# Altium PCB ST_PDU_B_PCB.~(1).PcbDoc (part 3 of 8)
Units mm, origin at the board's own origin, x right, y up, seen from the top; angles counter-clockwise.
Board outline 200 x 200 mm, 6 copper layers (Top Layer, Layer 1, Layer 2, Layer 3, Layer 4, Bottom Layer), stack 3.194 mm thick; 894 components, 723 nets, 3233 pads, 4067 vias.
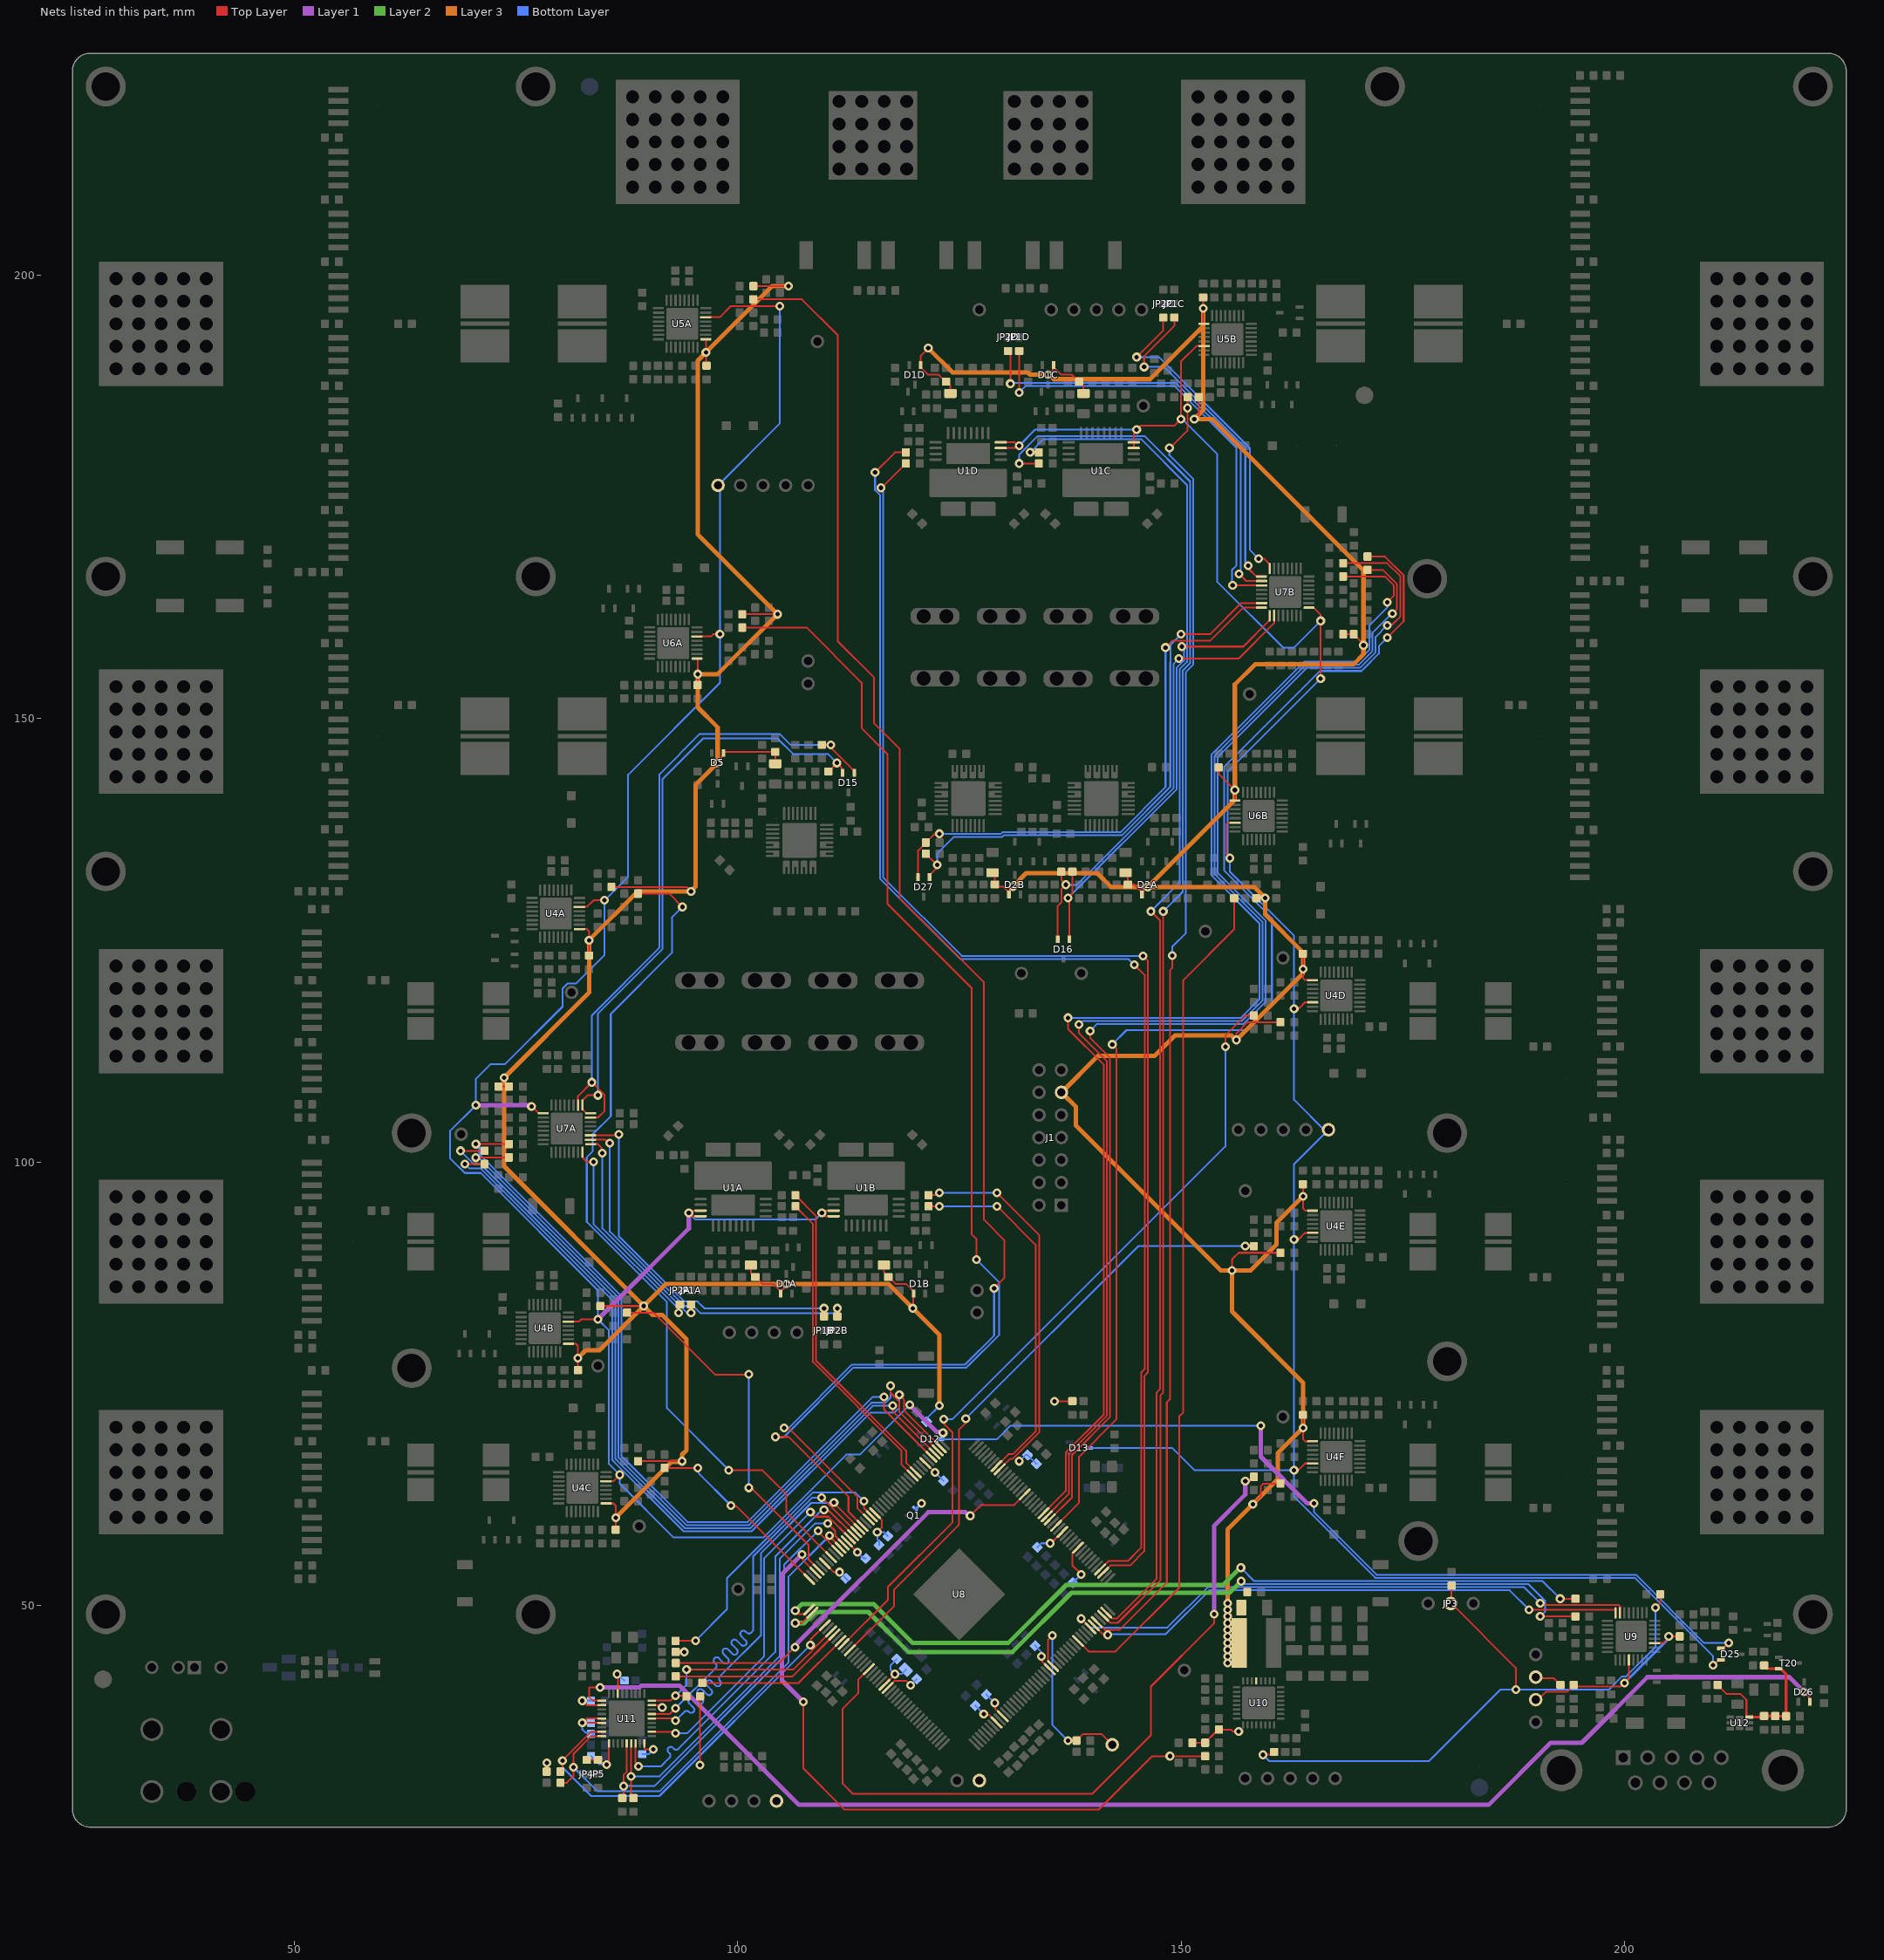
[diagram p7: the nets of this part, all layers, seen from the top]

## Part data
C1A C1B C1C C1D C5A C5B C5C C5D C8A C8B C15 C31A C31B C31C C31D C31E C31F C41A C41B C51A C51B C58A C58B C63 C64 C65 C66 C67 C68 C69 C70 C71 C72 C74 C109 C110 C111 C112 C114 C119: library part 100nF/50V_10%_0603, "100nF Ceramic capacitor", Package=0603, Tolerance=10%, Voltage=50V
C2A C2B C2C C2D C9A C9B C16: library part 1nF/50V_10%_0603, "1nF Ceramic capacitor", Package=0805, Tolerance=10%, Voltage=50V
C3A C3B C3C C3D C4A C4B C4C C4D C10A C10B C11A C11B C17 C18 C25A C25B C25C C25D C25E C25F C35A C35B C45A C45B C54A C54B C56A C56B C87 C99 C115 C116: library part 220nF/50V_10%_0603, "220nF Ceramic capacitor", Package=0603, Tolerance=10%, Voltage=50V
C6A C6B C6C C6D C7A C7B C7C C7D C13A C13B C14A C14B C20 C21 C22 C23 C32A C32B C32C C32D C32E C32F C42A C42B C52A C52B C73 C77 C79 C81 C83: library part 10nF/50V_10%_0603, "10nF Ceramic capacitor", Package=0603, Tolerance=10%, Voltage=50V
C12A C12B C19 C75 C84 C85 C92 C100: library part 2.2uF/16V_10%_0603, "2.2uF Ceramic capacitor", Package=0603, Tolerance=10%, Voltage=16V
C24A C24B C24C C24D C24E C24F C27A C27B C27C C27D C27E C27F C29A C29B C29C C29D C29E C29F C30A C30B C30C C30D C30E C30F C34A C34B C37A C37B C39A C39B C40A C40B C44A C44B C47A C47B C49A C49B C50A C50B C57A C57B C113 C118: library part 470nF/50V_10%_0603, "470nF Ceramic capacitor", Package=0603, Tolerance=10%, Voltage=50V
C26A C26B C26C C26D C26E C26F C28A C28B C28C C28D C28E C28F C36A C36B C38A C38B C46A C46B C48A C48B C88 C89 C90 C91 C108 C122 C123 C124: library part 1uF/50V_10%_0603, "1uF Ceramic capacitor", Package=0603, Tolerance=10%, Voltage=50V
C33A C33B C33C C33D C33E C33F C43A C43B C53A C53B C59A C59B C106: library part 1uF/16V_10%_0603, "1uF Ceramic capacitor", Package=0603, Tolerance=10%, Voltage=16V
C55A C55B: library part 22uF/50V_20%_CES_D_6.3, "22uF Electrolytic capacitor (EEHZC1H220P)", Tolerance=20%, Voltage=50V
C60 C61 C120 C121: library part 10pF/50V_10%_0603, "10pF Ceramic capacitor", Package=0603, Tolerance=10%, Voltage=50V
C62: library part 4,7uF/16V_10%_0805, "4,7uF Ceramic capacitor", Supplier Part Number 1=2112841, Tolerance=10%, Voltage=16V
C76 C78 C80 C82: library part 47nF/50V_10%_0603, "47nF Ceramic capacitor", Package=0603, Tolerance=10%, Voltage=50V
C86 C93 C94 C96 C97 C101 C102 C103 C104: library part 10uF/50V_10%_1206, "10uF Ceramic capacitor", Tolerance=10%, Voltage=50V
C95 C98: library part 100uF/50V_20%_CES_D_10, "100uF Electrolytic capacitor (EEHZC1H101V)", Tolerance=20%, Voltage=50V
C105 C107: library part 2,2uF/50V_10%_0805, "2,2uF Ceramic capacitor", Package=0805, Tolerance=10%, Voltage=50V
C117: library part 4,7nF/50V_10%_0603, "4.7nF Ceramic capacitor", Package=0603, Tolerance=10%, Voltage=50V
C125A C125B C125C C125D C125E C125F C126A C126B C127A C127B: library part 22uF/50V_20%_CES_D_6.3, "22uF Electrolytic capacitor (EEHZC1H220V)", Tolerance=20%, Voltage=50V
CR1: "No Description Available", Mfr_Name=STMicroelectronics
CR2: "ESD protection for automotive ethernet"
D1A D1B D1C D1D D2A D2B D5 D6A D6B D6C D6D D6E D6F D7A D7B D11A D11B D12 D13 D20 D21 D22 D23 D24 D28A D28B: "Automotive small signal Schottky diodes", Current=0.3A
D3A D3B D4 D25: "Automotive small signal dual Schottky diodes with common anode", Current=0.3A
D8A D8B D8C D8D D8E D8F D9A D9B D10A D10B: "40V/1A Automotive Schottky Diode STPS1L40-Y", Current=1A
D14A D14B D17 D18 D19: "60V/3A Automotive Schottky Diode STPS360-Y", Current=3A
D15 D16 D26 D27: library part BAT54C, "Automotive small signal dual Schottky diodes with common cathode", Current=0.3A
J2: "Header, 9-Pin, Right Angle", Supplier Part Number 1=1653975
J3: library part CMP-0078655-1, "Conn 1-Port 90° MATEnet Header, Code B", 2B Part Number=2BCONNECTPF00506, Manuf Code=2304372-2, Manufacturer="TE Connectivity"
JP1A JP1B JP1C JP1D JP2A JP2B JP2C JP2D: library part JUMP_3_PIN
JP6: Supplier Part Number 1="Header 2.54mmm 2way"
L1: library part 74438367100, "WE-MAPI, size 5030, 10uH, 3.3A, 70.2mOhm", Case/Size Code=5030, DC resistance=61mOhm, DC Resistance Max=70.2mOhm, Manufacturer="Wurth Elektronik", Operating Temperature Max=125°C, Operating Temperature Min=-40°C, Rated Current=3.3A, Saturation Current=4.8A, Self Resonant Frequency=13MHz
L2: library part LPS6235-153, "SMD Inductor; 15uH/20%/2,0A sat.; 6x6x3,5mm", DC resistance="0,125 Ohm", Rated Current=1.22A, Saturation Current=2,0A, Tolerance=20%
L3: library part 100uH/0,15A_+50%/-30%_1812, "Common Mode Choke for CAN", DC resistance="1,5 Ohm", Rated Current=0,15A, Supplier Part Number 1=1644874, Tolerance=+50/-30
L4: "Automotive ethernet CMMC", Mfr_Name=Murata
LED1: library part LED/RED_00603, Current=30mA
LED2 LED8 LED9: library part LED/ORANGE_0603, Current=30mA
LED3 LED4 LED5 LED6 LED7: library part LED/GREEN_0603, Current=30mA
LED10: library part LED/ORANGE_0603, "Orange LED", Current=30mA
P1 P2 P7 P8 P14 P15: "Pressfit M8 screw power connector (max 170A) with protector"
P3 P4 P5 P9 P10 P11: "Pressfit M6 screw power connector (max 80A) with protector"
P6 P12: "MTCon G&H 8pin power connector (max 40A/pin). Pressfit", Supplier Part Number 1=2035533
P13 P16: "Pressfit M5 screw power connector (max 80A) with protector"
Q1: "NPN Medium Power Transistor", Package=DFN2020-3
Q2: "N-Channel Enhancement Mode Vertical DMOS FET", Package=SOT23, Supplier Part Number 1=9845330
R1A R1B R1C R1D R15A R15B R29: library part 330R/150V_1%_0805, "Resistor SMD", Package=0805, Power Rating Per Resistor=125mW, Tolerance=1%, Voltage=150V
R2A R2B R2C R2D R16A R16B R30 R152 R153: library part 100R/0.1W_5%_0603, "Resistor SMD", Package=0603, Power=0.1W, Tolerance=5%
R3A R3B R3C R3D R17A R17B R31 R101A R101B: library part 330R/0.1W_5%_0603, "Resistor SMD", Package=0603, Power=0.1W, Tolerance=5%
R4A R4B R4C R4D R18A R18B R32: library part 120R/0.1W_5%_0603, "Resistor SMD", Package=0603, Power=0.1W, Tolerance=5%
R5A R5B R5C R5D R19A R19B R28A R28B R33 R42 R127 R154 R157 R163 R164 R192: library part 4k7/0.1W_5%_0603, "Resistor SMD", Package=0603, Power=0.1W, Tolerance=5%
R6A R6B R6C R6D R7A R7B R7C R7D R10A R10B R10C R10D R11A R11B R11C R11D R20A R20B R21A R21B R22A R22B R23A R23B R24A R24B R34 R35 R36 R37 R38 R48A R48B R48C R48D R48E R48F R57A R57B R57C R57D R57E R57F R58A R58B R58C R58D R58E R58F R59A R59B R59C R59D R59E R59F R67A R67B R77A R77B R78A R78B R80A R80B R87A R87B R97A R97B R98A R98B R99A R99B R102A R102B R103A R103B R104A R104B R105A R105B R106A R106B R107A R107B R156 R159 R162 R193 R194 R195 R196: library part 2k7/0.1W_5%_0603, "Resistor SMD", Package=0603, Power=0.1W, Tolerance=5%
R8A R8B R8C R8D R9A R9B R9C R9D R46 R52 R65 R123 R129 R130 R146 R147 R148 R149 R150 R151 R160 R161 R169 R185 R186 R188: library part 15k/0.1W_5%_0603, "Resistor SMD", Package=0603, Power=0.1W, Tolerance=5%
R12A R12B R12C R12D R13A R13B R13C R13D R25A R25B R26A R26B R39 R40 R49A R49B R49C R49D R49E R49F R51A R51B R51C R51D R51E R51F R68A R68B R70A R70B R88A R88B R90A R90B R108A R108B R109A R109B: library part 5k6/0.1W_5%_0603, "Resistor SMD", Package=0603, Power=0.1W, Tolerance=5%
R14A R14B R14C R14D R27A R27B R41 R50A R50B R50C R50D R50E R50F R69A R69B R89A R89B R110A R110B R155 R165: library part 180R/0.1W_5%_0603, "Resistor SMD", Package=0603, Power=0.1W, Tolerance=5%
R43A R43B R43C R43D R43E R43F: library part CurrentShunt_9W_3921, "High current shunt size 3921", Power Rating Per Resistor=9W, Voltage=150V
R44A R44B R44C R44D R44E R44F R47A R47B R47C R47D R47E R47F R53A R53B R53C R53D R53E R53F R61A R61B R62A R62B R63A R63B R66A R66B R72A R72B R74A R74B R79A R79B R81A R81B R83A R83B R86A R86B R92A R92B R95A R95B R100A R100B: library part 1R/0.1W_5%_0603, "Resistor SMD", Package=0603, Power=0.1W, Tolerance=5%
R45A R45B R45C R45D R45E R45F R55A R55B R55C R55D R55E R55F R64A R64B R75A R75B R84A R84B R94A R94B R122 R128 R166 R170 R171 R173 R174 R175 R176 R179 R180 R182: library part 47k/0.1W_5%_0603, "Resistor SMD", Package=0603, Power=0.1W, Tolerance=5%
R54A R54B R54C R54D R54E R54F R73A R73B R93A R93B: Package=0805, Supplier Part Number 1=1299914
R56A R56B R56C R56D R56E R56F R76A R76B R96A R96B R134 R172 R181 R190 R191: library part 10k/0.1W_5%_0603, "SMD Resistor Automotive", 2B Part Number=2BRESCHIPSF00800, Manufacturer=PANASONIC, Manufacturer P/N=ERJP03F1002V, Package=0603, Power=0.1W, Tolerance=1%
R60A R60B R82A R82B: library part CurrentShunt_15W_5930, "ISA-WELD precission resistor  BVE size 5630", Package=5930, Power Rating Per Resistor=15W, Voltage=150V
R71: library part 0R/0.1W_5%_0603, "Resistor SMD 0805", Package=0603, Power=0.1W, Tolerance=5%
R85 R91: library part 10k/0.1W_5%_0603, "Resistor SMD 0603", 2B Part Number=2BRESCHIPSF00800, Manufacturer=PANASONIC, Manufacturer P/N=ERJP03F1002V, Package=0603, Power=0.1W, Tolerance=1%
R111 R112 R113 R114 R115 R116 R117 R118 R197A R197B R198A R198B: library part 0R/0.1W_5%_0603, "Resistor SMD", Package=0603, Power=0.1W, Tolerance=5%
R119 R120 R121 R124 R125 R126 R131 R132 R133 R135 R136 R137 R139 R140 R141 R184: library part 47R/0.1W_5%_0603, "Resistor SMD", Package=0603, Power=0.1W, Tolerance=5%
R138 R142 R202: library part 1k5/0.1W_5%_0603, "Resistor SMD", Package=0603, Power=0.1W, Tolerance=5%
R143 R144 R145 R183: library part 100k/0.1W_5%_0603, "SMD Resistor", 2B Part Number=2BRESCHIPSF00800, Manufacturer=PANASONIC, Manufacturer P/N=ERJP03F1002V, Package=0603, Power=0.1W, Tolerance=1%
R158 R167 R168: library part 3k3/0.1W_5%_0603, "Resistor SMD", Package=0603, Power=0.1W, Tolerance=5%
R177 R178 R187: library part 1k/0.1W_5%_0603, "Resistor SMD", Package=0603, Power=0.1W, Tolerance=5%
R189: library part 30k/0.1W_5%_0603, "Resistor SMD", Package=0603, Power=0.1W, Tolerance=5%
R199: library part 360k/0.1W_5%_0603, "SMD Resistor", 2B Part Number=2BRESCHIPSF00800, Manufacturer=PANASONIC, Manufacturer P/N=ERJP03F1002V, Package=0603, Power=0.1W, Tolerance=1%
R200 R201: library part 200k/0.1W_5%_0603, "SMD Resistor", 2B Part Number=2BRESCHIPSF00800, Manufacturer=PANASONIC, Manufacturer P/N=ERJP03F1002V, Package=0603, Power=0.1W, Tolerance=1%
R203: library part 47k/0.1W_5%_0603, "Resistor SMD 0603", Package=0603, Power=0.1W, Tolerance=5%
R204 R205 R206A R206B: library part 47R/0.1W_5%_0603, "Resistor SMD 0603", Package=0603, Power=0.1W, Tolerance=5%
T1A T1B T1C T1D T2A T2B T3: "NPN", Supplier Part Number 1=1260803
T4A T4B T4C T4D T4E T4F T5A T5B T5C T5D T5E T5F T6A T6B T6C T6D T6E T6F T7A T7B T8A T8B T9A T9B T10A T10B T11A T11B T12A T12B T13A T13B T14A T14B T15A T15B T16A T16B T17A T17B T18A T18B T19A T19B: library part STL059N4S8AG, "Automotive N‑channel logic level 40 V, 0.59 mΩ max., 420 A Smart STripFET F8 / Power MOSFET in a PowerFLAT 5x6 package"
T20: "PNP", Supplier Part Number 1=1902487
TP1 TP2 TP3 TP4 TP5 TP6 TP7 TP8 TP9 TP10 TP11 TP12 TP13 TP14 TP15 TP16 TP17 TP18 TP19 TP20 TP21 TP22 TP23 TP24 TP25 TP26 TP27 TP28 TP29 TP30 TP31 TP32 TP33 TP34 TP35 TP36 TP37 TP38 TP39 TP40 TP41 TP42 TP43 TP44 TP45 TP46 TP47 TP48 TP49 TP50 TP51 TP52 TP53: library part "Test Point_1", "PCB ring test point - black (drill 1.32mm)", 2B Part Number=2BCONTESTPF00021, Manuf Code=262-2214, Manufacturer="RS PRO"
Tr_d3 Tr_d4 Tr_d10 Tr_d13: "30V 3000W unidirectional TVS in SMC", Power Rating=3000W
Tr_d18 Tr_d19: "39V 1500W unidirectional TVS in SMC", Power Rating=1500W
Tr_d20 Tr_d21: "18V 1500W unidirectional TVS in SMC", Power Rating=1500W, Supplier Part Number 1=9885676
U7A U7B: "Octa channel Smart P-channel MOSFET device. Used for standby power with STi2Fuse devices"
U8: "Chorus 6M, 3 cores, 6MB flash, LQFP176 package"
U9: library part SPSB081
U10: "SPSA068 PMIC with buck and precise voltage reference for MCU applications"
U11: "100BASE-T1 PHY for Automotive Ethernet"
U12: "Adjustable 200mA LDO"
X1: library part CX3225CA40000D0HSSZ1, "CRYSTAL 40.000MHZ 8PF SMD Automotive -40/+125"
X2: library part CX3225CA25000D0HSSZ1, "CRYSTAL 25.000MHZ 8PF SMD Automotive -40/+125"
ZD1A ZD1B ZD1C ZD1D ZD1E ZD1F ZD2A ZD2B ZD3A ZD3B: "5,6V Zener Diode", Power Rating=200mW

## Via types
v1: diameter 0.65/1/1/1/1/0.65 (per signal layer), hole 0.5, Top Layer to Bottom Layer, 3739 vias
v2: diameter 0.65/1/1/1/1/0.65 (per signal layer), hole 0.5, Top Layer to Bottom Layer, tented both sides, 296 vias
v3: diameter 0.65, hole 0.5, Top Layer to Bottom Layer, 32 vias

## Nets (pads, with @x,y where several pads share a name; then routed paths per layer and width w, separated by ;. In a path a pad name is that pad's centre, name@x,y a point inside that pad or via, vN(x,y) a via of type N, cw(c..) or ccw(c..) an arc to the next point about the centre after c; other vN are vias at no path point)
3V3: C1A.2 C1B.2 C1C.2 C1D.2 C8A.2 C8B.2 C15.2 C31A.2 C31B.2 C31C.2 C31D.2 C31E.2 C31F.2 C41A.2 C41B.2 C51A.2 C51B.2 C58A.2 C58B.2 C62.2 C63.2 C64.2 C65.2 C66.2 C67.2 C68.2 C69.2 C70.2 C71.2 C72.2 C73.2 C74.2 C86.2 C87.2 C109.2 C110.2 C114.2 C115.2 C116.2 C118.2 D1A.1 D1B.1 D1C.1 D1D.1 D2A.1 D2B.1 D5.1 J1.11 JP4.3 JP5.2 JP6.2 L1.2 LED10.A Q1.2 R1A.2 R1B.2 R1C.2 R1D.2 R15A.2 R15B.2 R29.2 R55A.1 R55B.1 R55C.1 R55D.1 R55E.1 R55F.1 R75A.1 R75B.1 R94A.1 R94B.1 R101A.1 R101B.1 R122.1 R127.1 R128.1 R158.1 R167.1 R168.1 R176.1 R181.2 R182.1 R193.2 TP3.1 TP6.1 U4A.1 U4B.1 U4C.1 U4D.1 U4E.1 U4F.1 U5A.1 U5B.1 U6A.1 U6B.1 U8.25 U8.26 U8.52 U8.54 U8.69 U8.99 U8.104 U8.139 U8.155 U8.164 U8.171 U10.5 U11.7 U11.11 U11.14 U11.15 U11.19 U11.27 U11.35 | length 752.4
  Top Layer w0.2: v1(73.675,109.5) 73.608,109.433 73.608,109.108 73.025,108.525 R101A.1@73.025,108.5 C58A.2@74.225,108.5 ; R176.1@78.475,31.25 78.5,31.275 v1(78.5,32.25) ; U4B.1@80.927,79.5 81.75,79.5 82,79.25 v1(82,77.887) C31B.2@82,76.525 ; U4A.1@82.177,126.25 83,126.25 83.25,126 v1(83.25,125) C31A.2@83.25,123.275 C31A.2@83.25,123.144 ; v1(82.5,39.25) 83,38.75 U11.11@84.3,38.75 ; JP4.3@83,32.575 JP5.2@84.25,32.575 84.575,32.25 84.878,32.25 85.097,32.032 v1(85.218,32.032) 85.218,32.153 85.5,32.435 U11.19@85.5,34.05 ; R55B.1@84.552,83.75 v1(89.425,83.75) ; U11.15@84.683,36.75 v1(82.5,36.75) 83,37.25 U11.14@84.683,37.25 ; U4C.1@85.177,61.5 86,61.5 86.25,61.25 v1(86.25,59.888) C31C.2@86.25,58.525 C31C.2@86.25,58.394 ; R55A.1@85.775,131 94.25,131 v1(94.75,130.5) ; v1(86.425,42.25) 86.5,42.175 U11.7@86.5,40.45 ; R55C.1@88.775,66.25 v1(93.75,66.25) ; U11.27@89.5,34.05 89.5,33.867 89.617,33.75 v1(90.5,33.75) ; U11.35@90.317,38.75 91.128,38.75 91.378,38.5 v1(91.5,38.5) ; R182.1@93.025,44.75 v1(94,44.75) ; U6A.1@95.427,156.75 95.473,156.75 95.5,156.723 v1(95.5,155) C51A.2@95.5,153.775 ; v1(95.75,32) 95.775,32.025 R181.2@95.775,39.75 ; C41A.2@96.427,189.775 v1(96.427,191.263) U5A.1@96.427,192.75 ; v1(97.75,145) 97.836,145.086 97.836,145.312 98.4,145.876 D5.1@98.4,146.108 98.4,146.147 98.503,146.25 104.225,146.25 C15.2@104.25,146.225 R29.2@104.25,144.893 ; R94A.1@100.525,161.75 v1(104.5,161.75) ; R1A.2@101.5,88.357 101.5,87.507 101.982,87.025 C1A.2@102,87.025 ; R75A.1@101.775,198.75 v1(105.75,198.75) ; C1A.2@102.025,87.025 102.8,86.25 104,86.25 104.747,85.503 D1A.1@104.747,85.271 ; D1A.1@104.747,85.245 D1A.1@104.747,85.271 ; v1(105.5,86.25) 105.414,86.164 105.414,85.938 D1A.1@104.747,85.271 ; U8.171@109.843,54.74 110.833,53.75 v1@111.25,53.75 ; U8.164@112.318,57.214 112.318,57.198 113.5,56.016 v1(113.5,56) ; U8.155@115.5,60.396 116.25,59.646 116.25,58.75 v1(115.75,58.25) ; R1B.2@116.5,88.357 116.5,87.525 116.517,87.508 116.633,87.392 116.633,87.374 116.982,87.025 C1B.2@117,87.025 117.025,87.025 117.8,86.25 119,86.25 119.747,85.503 119.747,85.245 D1B.1@119.85,85.142 119.8,85.092 119.8,83.55 v1(119.75,83.5) ; U8.25@116.561,41.043 116.561,41.052 117.75,42.241 v1(117.75,42.25) ; U8.26@116.914,40.689 117.725,41.5 119,41.5 v1(119.5,41) ; U8.139@121.157,66.053 121.177,66.053 122.23,65 v1(122.25,65) ; v1(121.5,191.75) 120.65,190.9 D1D.1@120.65,189.858 120.753,189.755 120.753,189.497 121.5,188.75 122.7,188.75 123.475,187.975 C1D.2@123.5,187.975 123.518,187.975 124,187.493 R1D.2@124,186.643 ; v1(127.75,37.75) 127.836,37.664 128.333,37.664 U8.52@129.197,36.8 ; R15B.2@128.75,132.607 128.98,132.377 128.98,131.295 C8B.2@129,131.275 129.238,131.037 129.936,131.037 130.6,130.374 D2B.1@130.6,130.142 130.673,130.214 130.673,130.673 v1(131.064,131.064) ; v1(129,39) 129.036,38.964 129.036,38.375 U8.54@129.904,37.507 ; v1(134.25,44.25) 134.336,44.164 134.336,43.682 U8.69@135.207,42.811 ; v1(135,188.75) 135.547,189.297 135.547,189.755 D1C.1@135.65,189.858 135.753,189.755 135.753,189.497 136.5,188.75 137.7,188.75 138.475,187.975 C1C.2@138.5,187.975 138.518,187.975 139,187.493 R1C.2@139,186.643 ; v1(135.25,57) 135.346,57 U8.104@136.621,58.275 ; v1(135.75,73) 137.725,73 LED10.A@137.75,73.025 ; U8.99@138.389,56.507 138.389,56.48 137.75,55.841 137.75,54.5 v1(138.75,53.5) ; R15A.2@143.5,132.5 143.697,132.5 144,132.197 C8A.2@144,131.275 144.699,131.275 D2A.1@145.6,130.374 ; D2A.1@145.6,130.142 D2A.1@145.6,130.374 ; v1(146.25,131) 146.226,131 D2A.1@145.6,130.374 ; R168.1@151.275,34.5 R167.1@152.725,34.5 152.725,34.525 153.833,35.633 153.926,35.633 154.275,35.982 R158.1@154.275,36 155.653,36 155.878,35.775 v1(156.505,35.775) ; v1(151.5,183.75) 152,184.25 R75B.1@152,186.225 ; C41B.2@152.5,197.475 v1(152.5,196.25) 152.5,194.527 152.527,194.5 U5B.1@152.573,194.5 ; C51B.2@154.25,144.475 154.25,143.75 v1(156.073,141.927) U6B.1@156.073,140.75 ; v1(155.75,87.75) 155.75,89 156.5,89.75 R55E.1@161.225,89.75 ; v1(156.25,113.75) 156.25,114.5 157.5,115.75 R55D.1@161.225,115.75 ; v1(158.093,61.407) 159,62.313 159,63.438 159.287,63.725 161.2,63.725 R55F.1@161.225,63.75 ; R94B.1@158.5,129.725 158.525,129.75 v1(159.5,129.75) ; C31F.2@163.75,71.606 C31F.2@163.75,71.475 v1(163.75,70) 163.75,68.75 164,68.5 U4F.1@164.823,68.5 ; C31E.2@163.75,97.475 v1(163.75,96.113) 163.75,94.75 164,94.5 U4E.1@164.823,94.5 ; C31D.2@163.75,123.606 C31D.2@163.75,123.475 v1(163.75,121.75) 163.75,120.75 164,120.5 U4D.1@164.823,120.5 ; C58B.2@168.275,159.5 R101B.1@169.475,159.5 169.475,159.468 170.575,158.368 v1(170.575,158.25) ; TP6.1@190.123,41.787 191.999,41.787 192.761,41.025 R193.2@192.786,41.025
  Layer 3 w0.5: v1(82,77.887) 82.863,78.75 84.425,78.75 v1(89.425,83.75) ; v1(86.25,59.888) 92.517,66.154 93.654,66.154 v1(93.75,66.25) 93.75,67 94.25,67.5 94.25,80 91.5,82.75 90.425,82.75 v1(89.425,83.75) ; v1(105.75,198.75) 105.741,198.741 103.906,198.741 v1(96.427,191.263) 95.5,190.335 95.5,170.75 v1(104.5,161.75) 97.75,155 v1(95.5,155) 95.5,151.25 97.75,149 v1(97.75,145) 95.25,142.5 95.25,131.043 94.75,130.543 v1(94.75,130.5) 88.75,130.5 v1(83.25,125) 83.25,119.075 v1(73.675,109.5) 73.675,99.5 v1(89.425,83.75) ; v1(121.5,191.75) 124.25,189 132.741,189 132.991,188.75 v1(135,188.75) 135.135,188.75 135.635,188.25 146.5,188.25 152.5,194.25 ; v1(122.75,72.5) 122.75,80.5 v1(119.75,83.5) 117,86.25 v1(105.5,86.25) 91.925,86.25 v1(89.425,83.75) ; v1(131.064,131.064) 132.55,132.55 140.554,132.55 142.104,131 v1(146.25,131) ; v1(152.5,196.25) 152.5,194.25 ; v1(155.25,50.25) 155.25,58.563 v1(158.093,61.407) 160.922,64.235 160.922,67.172 v1(163.75,70) 163.75,75.125 155.75,83.125 v1(155.75,87.75) ; v1(163.75,96.113) 160.75,93.113 160.75,90.662 157.838,87.75 v1(155.75,87.75) ; v1(146.25,131) 158.25,131 v1(159.5,129.75) 159.5,127.875 163.75,123.625 v1(163.75,121.75) 163.712,121.712 163.712,121.212 v1(156.25,113.75) 156.196,113.75 155.696,114.25 149.312,114.25 147.012,111.95 140.64,111.95 J1.11@136.52,107.83 138.16,106.19 138.16,104.077 154.487,87.75 v1(155.75,87.75) ; v1(146.25,131) 156.035,140.785 156.035,141.889 v1(156.073,141.927) 156.073,153.823 158.348,156.098 169.437,156.098 170.575,157.237 v1(170.575,158.25) 170.575,166.675 153.5,183.75 v1(151.5,183.75) 152.5,184.75 152.5,194.25
  Bottom Layer w0.2: v1(82.5,39.25) C116.2@83.475,39.25 C116.2@83.7,39.25 ; C110.2@83.475,33 83.475,32.982 83.824,32.633 83.842,32.633 84.368,32.107 85.143,32.107 v1(85.218,32.032) ; C114.2@83.725,35.5 83.567,35.658 82.842,35.658 82.5,36 v1(82.5,36.75) C115.2@83.725,36.75 ; v1(86.425,42.25) 86.493,42.25 87.218,41.525 C118.2@87.25,41.525 ; C109.2@89.25,33.225 89.975,33.225 v1(90.5,33.75) ; v1(111.5,53.75) C67.2@112.202,53.048 C67.2@112.452,52.798 ; v1(113.5,56) 114.202,55.298 C74.2@114.452,55.298 ; C73.2@115.952,56.798 115.952,57.221 115.75,57.423 v1(115.75,58.25) 116.5,58.25 C72.2@116.952,57.798 ; C63.2@117.952,43.952 117.25,43.25 117.25,42.75 v1(117.75,42.25) 118.487,42.25 C62.2@118.981,42.743 ; v1(119.5,41) C70.2@120.202,41.702 ; R122.1@121.298,70.702 121.298,71.048 v1(122.75,72.5) ; v1(122.25,65) C66.2@123.202,64.048 ; C69.2@126.798,38.702 v1(127.75,37.75) ; C68.2@128.048,39.952 v1(129,39) ; v1(131.75,66.25) 132.452,66.952 R127.1@132.702,66.952 R128.1@133.702,65.952 ; C64.2@133.548,45.452 134.25,44.75 v1(134.25,44.25) ; C71.2@133.798,56.548 134.25,57 v1(135.25,57) ; C65.2@137.798,52.548 v1(138.75,53.5)
  Bottom Layer w0.3: Q1.2@120.018,60.901 120.048,60.872 120.122,60.872 v1(120.75,61.5)
  other v1: 155.25,43.5 155.25,44.25 155.25,45 155.25,45.75 155.25,46.5 155.25,47.25 155.25,48 155.25,48.75 155.25,49.5
3V3_STB: C106.2 R171.1 R194.2 R199.1 R200.2 T20.2 U12.6 | length 18.1
  Top Layer w0.2: R194.2@210.5,41.025 210.525,41.025 211.55,40 213.098,40 213.75,39.348 213.75,37.725 213.765,37.71 213.765,37.5 213.865,37.4 U12.6@214.075,37.4 ; R200.2@215.625,37.525 R200.2@215.75,37.525
  Top Layer w0.3: U12.6@214.075,37.4 215.625,37.4 R200.2@215.75,37.525 C106.2@217,37.525 217.012,37.513 218.212,37.513 R199.1@218.225,37.5 218.225,42.249 217.624,42.85 T20.2@217.392,42.85 216.15,42.85 215.775,43.225 R171.1@215.75,43.225
5V: C92.2 R192.1 TP5.1 U9.3 U9.28 | length 25.2
  Top Layer w0.2: TP5.1@189.992,39.116 191.126,40.25 193.538,40.25 193.919,40.631 193.919,40.676 194.029,40.786 194.286,40.786 R192.1@194.286,41.025 ; R192.1@194.071,40.965 R192.1@194.148,40.888 ; R192.1@194.071,41.025 R192.1@194.286,41.025 ; R192.1@194.13,40.888 R192.1@194.148,40.888 ; U9.28@200.5,43.848 200.5,41.75 v1(200,41.25) 199.966,41.25 199.541,40.825 194.361,40.825 194.286,40.75 R192.1@194.148,40.888 ; U9.3@203.402,45.75 204.372,45.75 205,46.378 v1(205,46.5) C92.2@206.225,46.5 ; R192.1@194.148,40.888 R192.1@194.286,41.025
  Bottom Layer w0.3: v1(200,41.25) 204.933,46.183 204.933,46.433 v1(205,46.5)
CAN1_RX: R153.1 U8.2 | length 99.6
  Top Layer w0.2: v1(106.5,48) 107.254,48 U8.2@108.429,49.175 ; v1(190.5,48.75) R153.1@194.475,48.75
  Layer 2 w0.5: v1(106.5,48) 107.5,48 108.75,49.25 114.75,49.25 119.25,44.75 130.996,44.75 137.656,51.409 155.465,51.409 v1(156.778,52.722)
  Bottom Layer w0.2: v1(156.778,52.722) 157.1,52.4 189.163,52.4 191.075,50.488 191.075,49.325 v1(190.5,48.75)
CAN1_TX: R152.2 U8.1 | length 97
  Top Layer w0.2: v1(106.5,49.4) 106.9,49 107.499,49 108.027,49.528 U8.1@108.075,49.528 ; v1(192.75,50.75) R152.2@194.475,50.75
  Layer 2 w0.5: v1@106.5,49.404 107.246,50.15 115.35,50.15 119.75,45.75 130.5,45.75 137.059,52.309 154.738,52.309 156.679,54.25 v1@156.746,54.25
  Bottom Layer w0.2: v1(156.75,54.25) 158.25,52.75 190.75,52.75 v1(192.75,50.75)
DEBUG: JP3.1 R71.2 R85.2 R91.1 | length 72.3
  Top Layer w0.2: v1(159.25,33.15) 159.294,33.194 160.219,33.194 R91.1@160.5,33.475 ; R71.2@180.5,52.225 180.5,50.293 JP3.1@180.408,50.202 180.502,50.202 187.75,42.954 v1(187.75,40.5) ; v1(203.5,49.75) 204.025,50.275 R85.2@204.025,51.25
  Bottom Layer w0.2: v1(159.25,33.15) 159.975,32.425 177.925,32.425 186,40.5 v1(187.75,40.5) 198.25,40.5 199.75,42 200.184,42 203.5,45.316 v1(203.5,49.75)
DI0_A14: R103A.2 U8.137 | length 93.2
  Top Layer w0.2: v1(70.5,102) R103A.2@74.225,102 ; v1(116.5,73.5) 116.5,72.124 U8.137@121.864,66.76
  Bottom Layer w0.2: v1(70.5,102) 70.9,101.6 70.9,100.865 86.9,84.865 86.9,66.855 87.15,66.605 87.15,66.6 94.35,59.4 101.15,59.4 115.253,73.503 116.497,73.503 v1(116.5,73.5)
DI0_B14: R103B.2 U8.110 | length 149.9
  Top Layer w0.2: U8.110@134.5,60.396 137,62.896 137,67.235 141.3,71.535 141.3,110.95 137.25,115 v1(137.25,116.25) ; R103B.2@168.275,166 173,166 174,165 174,163.86 v1(173.24,163.1)
  Bottom Layer w0.2: v1(137.25,116.25) 156.745,116.25 158.85,118.355 158.85,126.895 153.45,132.295 153.45,145.95 163.9,156.4 169.9,156.4 171.25,157.75 171.25,160.5 173.24,162.49 v1(173.24,163.1)
DI1_A14: R104A.2 U8.136 | length 92.7
  Top Layer w0.2: v1(68.75,101.25) R104A.2@71.475,101.25 ; v1(117.5,72.5) 117.5,71.831 U8.136@122.218,67.114
  Bottom Layer w0.2: v1(68.75,101.25) 70.25,99.75 71.025,99.75 86.2,84.575 86.2,66.565 86.45,66.315 86.45,66.3 94.05,58.7 101.45,58.7 115.248,72.498 117.498,72.498 v1(117.5,72.5)
DI1_B14: R104B.2 U8.109 | length 146.6
  Top Layer w0.2: U8.109@134.854,60.043 137.35,62.539 137.35,67.09 141.65,71.39 141.65,71.4 141.65,111.35 138.5,114.5 v1(138.5,115.5) ; R104B.2@171.025,166.75 172.745,166.75 174.35,165.145 174.35,162.342 173.838,161.83 v1(173.829,161.83)
  Bottom Layer w0.2: v1(138.5,115.5) 138.9,115.9 156.89,115.9 159.2,118.21 159.2,127.04 153.8,132.44 153.8,145.795 164.055,156.05 170.045,156.05 170.245,156.25 170.25,156.25 171.6,157.6 171.6,159.663 173.767,161.83 v1(173.829,161.83)
DI2_A14: R105A.2 U8.135 | length 95
  Top Layer w0.2: v1(70.475,100.477) 70.498,100.5 R105A.2@74.225,100.5 ; v1(117.25,74.75) 117.25,73.937 118.25,72.937 118.25,71.789 U8.135@122.571,67.467
  Bottom Layer w0.2: v1(70.475,100.477) 70.539,100.414 70.856,100.414 86.55,84.72 86.55,66.71 86.8,66.46 86.8,66.455 94.205,59.05 101.305,59.05 115.103,72.848 116.661,72.848 117.25,73.437 v1(117.25,74.75)
DI2_B14: R105B.2 U8.108 | length 149.6
  Top Layer w0.2: U8.108@135.207,59.689 137.7,62.182 137.7,66.945 142,71.245 142,71.255 142,111.495 142,111.75 139.75,114 v1(139.75,114.75) ; R105B.2@168.275,167.5 173.25,167.5 174.75,166 174.75,161.5 173.836,160.586 173.336,160.586 v1(173.25,160.5)
  Bottom Layer w0.2: v1(139.75,114.75) 140.55,115.55 157.035,115.55 159.55,118.065 159.55,127.185 154.15,132.585 154.15,145.65 164.2,155.7 170.2,155.7 171.95,157.45 171.95,159.2 v1(173.25,160.5)
DI3_A14: R106A.2 U8.134 | length 94
  Top Layer w0.2: v1(69.25,99.75) R106A.2@71.475,99.75 ; v1(118.25,73.75) 118.25,73.725 118.75,73.225 118.75,71.996 U8.134@122.925,67.821
  Bottom Layer w0.2: v1(69.25,99.75) 69.75,99.25 71.03,99.25 85.85,84.43 85.85,66.42 86.1,66.17 86.1,66.155 93.905,58.35 101.6,58.35 115,71.75 117.689,71.75 118.25,72.311 v1(118.25,73.75)
DI3_B14: R106B.2 U8.106 | length 143.8
  Top Layer w0.2: U8.106@135.914,58.982 138.5,61.568 138.5,66.75 142.7,70.95 142.7,112.8 v1(142.25,113.25) ; R106B.2@171.025,168.25 172.995,168.25 175.1,166.145 175.1,160.95 v1(173.25,159.1)
  Bottom Layer w0.2: v1(142.25,113.25) 143.85,114.85 157.35,114.85 160.25,117.75 160.25,127.475 154.85,132.875 154.85,144.537 165.663,155.35 170.345,155.35 170.495,155.5 170.5,155.5 172.3,157.3 172.3,158.15 v1(173.25,159.1)
DI_A1: R77A.2 U8.157 | length 174.8
  Top Layer w0.2: R77A.2@101.775,197.25 107.25,197.25 111.3,193.2 111.3,159 111.3,158.7 115.383,154.617 115.383,149.467 118.3,146.55 118.3,129.7 127.78,120.22 127.78,93.475 130.075,91.18 130.075,86.9 v1(128.925,85.75) ; v1(105.25,70) 105.75,70 113.5,62.25 113.5,60.982 U8.157@114.793,59.689
  Bottom Layer w0.2: v1(105.25,70) 105.75,70 112.9,77.15 125.645,77.15 125.745,77.25 125.75,77.25 128.925,80.425 v1(128.925,85.75)
DI_A2: R97A.2 U8.159 | length 141
  Top Layer w0.2: R97A.2@100.525,160.25 107.76,160.25 113.983,154.028 113.983,148.887 116.9,145.97 116.9,129.105 126.38,119.625 126.38,91.87 126.925,91.325 v1(126.925,89) ; v1(104.25,69) 105.755,69 112.5,62.255 112.5,60.568 U8.159@114.086,58.982
  Bottom Layer w0.2: v1(104.25,69) 105.25,69 113.05,76.8 125.795,76.8 125.995,77 126,77 129.5,80.5 129.5,86.425 v1(126.925,89)
DI_A3: R57A.2 U8.169 | length 97
  Top Layer w0.2: R57A.2@88.775,130.25 92.27,130.25 v1(93.77,128.75) ; v1(99,65.25) 102.75,65.25 105.5,62.5 105.5,60.497 U8.169@110.55,55.447
  Bottom Layer w0.2: v1(93.77,128.75) 92.6,127.58 92.6,123.572 85.7,116.672 85.7,105.147 83.652,103.098 83.652,101.162 82.995,100.505 82.995,93.24 92.025,84.21 92.025,72.225 v1(99,65.25)
DI_A4: R57B.2 U8.173 | length 42.1
  Top Layer w0.2: R57B.2@87.525,83 90.5,83 97.5,76 101.2,76 v1(101.25,76.05) ; v1(101.25,63.25) 101.336,63.164 101.631,63.164 108,56.795 108,55.169 U8.173@109.136,54.032
  Bottom Layer w0.2: v1(101.25,63.25) v1(101.25,76.05)
DI_A5: R57C.2 U8.176 | length 21.8
  Top Layer w0.2: R57C.2@91.775,65.5 91.784,65.491 v1(95.501,65.491) ; v1(99.25,61.25) 99.328,61.172 99.875,61.172 U8.176@108.075,52.972
  Bottom Layer w0.2: v1(95.501,65.491) 95.588,65.405 95.588,64.912 v1(99.25,61.25)
DI_B1: R77B.2 U8.84 | length 147.3
  Top Layer w0.2: U8.84@140.51,48.114 140.537,48.114 141.401,47.25 143.08,47.25 148.4,52.57 148.4,72.9 148.75,73.25 148.75,121.61 149,121.86 v1(149,123.25) ; v1(148.694,180.493) 148.743,180.493 150.75,182.5 v1(150.75,185) R77B.2@150.75,186.225
  Bottom Layer w0.2: v1(148.694,180.493) 148.694,179.68 151.381,176.993 151.381,156.083 150.542,155.244 150.542,125.792 149,124.25 v1(149,123.25)
DI_B2: R97B.2 U8.78 | length 95.2
  Top Layer w0.2: U8.78@138.389,45.993 139.582,44.8 142.61,44.8 149.8,51.99 149.8,71.3 150.25,71.75 150.25,120.5 156,126.25 R97B.2@156,129.725
DI_B3: R57D.2 U8.12 | length 92
  Top Layer w0.2: U8.12@111.964,45.639 116.95,50.625 116.95,52.064 124.25,59.364 124.25,69.467 123.25,70.467 v1(123.25,71) ; v1(155,113) 155.001,113.001 155.001,114.251 157.25,116.5 R57D.2@158.225,116.5
  Bottom Layer w0.2: v1(123.25,71) 124.25,71 154.998,101.748 154.998,112.998 v1(155,113)
DI_B4: R57E.2 U8.14 | length 72.1
  Top Layer w0.2: U8.14@112.672,44.932 117.65,49.91 117.65,51.774 124.95,59.074 124.95,69.775 125.73,70.555 v1(125.73,71.05) ; v1(157.25,90.5) R57E.2@158.225,90.5
  Bottom Layer w0.2: v1(125.73,71.05) 145.18,90.5 v1(157.25,90.5)
DI_B5: R57F.2 U8.20 | length 86.3
  Top Layer w0.2: U8.20@114.793,42.811 113.6,41.618 113.6,40.1 111.85,38.35 111.85,29.9 113,28.75 140.005,28.75 146.6,35.345 146.6,40.85 153.75,48 v1(153.75,49) ; v1(157.25,64) 157.743,64 158.225,64.482 R57F.2@158.225,64.5
  Layer 1 w0.5: v1(153.75,49) 153.75,59 157.25,62.5 v1(157.25,64)
DIAG_A: D12.3 D25.1 TP21.1 U1A.9 U1A.10 U1B.9 U1B.10 U4A.6 U4B.6 U4C.6 U5A.6 U6A.6 U7A.1 | length 375.1
  Top Layer w0.2: v1(76.757,106.264) 76.811,106.264 77.575,105.5 U7A.1@78.073,105.5 ; U4B.6@80.902,82 82.128,82 82.378,82.25 v1(84.25,82.25) ; U4A.6@82.152,128.75 83.01,128.75 83.76,129.5 v1(85,129.5) ; U4C.6@85.152,64 86,64 v1(86.721,64.721) ; U6A.6@95.402,159.25 97,159.25 97.25,159.5 v1(98,159.5) ; U1A.10@95.83,93.864 94.886,93.864 v1(94.5,94.25) 94.622,94.25 94.867,94.495 95.811,94.495 U1A.9@95.83,94.514 ; U5A.6@96.402,195.25 98,195.25 99.25,196.5 v1(104.75,196.5) ; U1B.10@110.83,93.864 109.886,93.864 v1(109.5,94.25) 109.566,94.25 109.83,94.514 U1B.9@110.83,94.514 ; D25.1@210.892,45.15 211.124,45.15 211.724,45.75 v1(211.75,45.75)
  Layer 1 w0.5: v1(70.5,106.4) 76.486,106.4 76.622,106.264 v1(76.757,106.264) ; v1(84.25,82.25) 94.5,92.5 v1(94.5,94.25) ; v1(119.396,72.604) 122.455,69.545 123.068,69.545 v1(123.164,69.449) ; v1(159,70.25) 159,66.75 164.241,61.509 164.991,61.509 v1(165,61.5)
  Bottom Layer w0.2: v1(94.5,94.25) 95.25,93.5 108.75,93.5 v1(109.5,94.25) ; TP21.1@97.79,176.276 104.75,183.236 v1(104.75,196.5) ; TP21.1@98,176.276 v1(98,159.5) 98,153.995 87.65,143.645 87.65,132.15 v1(85,129.5) 85,123.341 81.797,120.138 80.861,120.138 80.268,119.545 80.268,117.513 73.753,110.998 72.136,110.998 70.5,109.362 v1(70.5,106.4) 67.564,103.464 67.564,100.436 69.25,98.75 71.035,98.75 84.25,85.535 v1(84.25,82.25) 85.5,81 85.5,65.942 v1(86.721,64.721) 86.721,63.716 92.787,57.65 102.9,57.65 112.25,67 113.792,67 v1(119.396,72.604) ; D12.3@122.858,68.75 D12.3@123.061,68.75 ; v1(123.164,69.449) 123.164,68.853 D12.3@123.061,68.75 ; v1(159,70.25) 130.75,70.25 129.25,68.75 D12.3@123.061,68.75 ; v1(165,61.5) 165,60.495 172.045,53.45 201.295,53.45 208.995,45.75 v1(211.75,45.75)
DIAG_B: D13.3 D25.2 TP32.1 U1C.9 U1C.10 U1D.9 U1D.10 U4D.6 U4E.6 U4F.6 U5B.6 U6B.6 U7B.1 | length 277.1
  Top Layer w0.2: U1D.9@129.67,180.486 131.364,180.486 131.628,180.75 v1@131.638,180.75 ; U1D.10@129.67,181.136 131.252,181.136 v1@131.638,180.75 ; v1(131.75,180.75) v1@131.638,180.75 ; U1C.9@144.67,180.486 U1C.10@144.67,181.136 144.67,182.123 145,182.453 v1(145,182.575) 145.425,183 149.25,183 v1(150,183.75) 150,190.25 151.75,192 U5B.6@152.598,192 ; v1(155.5,134.25) 155.5,134.372 155.133,134.739 155.133,138.133 155.25,138.25 U6B.6@156.098,138.25 ; v1(162.75,65.25) 163.24,65.25 163.99,66 U4F.6@164.848,66 ; v1(162.75,91.25) 163.24,91.25 163.99,92 U4E.6@164.848,92 ; v1(162.75,117.25) 162.836,117.336 163.336,117.336 164,118 U4D.6@164.848,118 ; U7B.1@164.427,162.5 164.454,162.473 164.952,162.473 165.75,161.675 v1(165.75,161) v1(165.75,154.5) ; v1(210,43.25) 210.059,43.25 210.659,43.85 D25.2@210.892,43.85
  Bottom Layer w0.2: v1(131.75,180.75) 133.575,182.575 v1(145,182.575) ; D13.3@139.608,67.75 149,67.75 151.5,65.25 v1(162.75,65.25) ; v1(150,183.75) 150.122,183.75 150.301,183.571 150.305,183.571 154.1,179.776 154.1,165.4 161.5,158 162.75,158 v1(165.75,161) ; v1(165.75,154.5) 155.25,144 155.25,134.592 155.5,134.342 v1(155.5,134.25) 155.5,132.75 162.75,125.5 v1(162.75,117.25) 162.75,106.998 TP32.1@166.37,103.378 ; TP32.1@166.624,103.632 TP32.1@166.37,103.378 ; v1(210,43.25) 210,44.25 201.15,53.1 171.9,53.1 162.75,62.25 v1(162.75,65.25) ; v1(162.75,65.25) v1(162.75,91.25) 162.75,99.758 TP32.1@166.37,103.378
DIAGN: U8.82 U9.15 | length 66.4
  Top Layer w0.2: v1(138.75,48.5) 138.75,48.48 139.803,47.427 U8.82@139.803,47.407 ; v1(190.5,50.25) 190.617,50.25 190.842,50.025 199.374,50.025 199.491,49.908 199.491,48.986 U9.15@199.5,48.977
  Bottom Layer w0.2: v1(138.75,48.5) 139.75,47.5 148.462,47.5 153.012,52.05 188.7,52.05 v1(190.5,50.25)
EM0_A6: R6A.2 U8.143 | length 35.8
  Top Layer w0.2: R6A.2@106.525,95 106.525,94.975 108.5,93 108.5,77.437 118.469,67.469 118.469,65.913 U8.143@119.743,64.639
EM0_A8: R6B.2 U8.125 | length 40.9
  Top Layer w0.2: R6B.2@121.525,95 v1(122.75,95) ; U8.125@129.197,65.7 130.541,67.045 131.045,67.045 133.6,69.6 133.6,90.65 v1(129.25,95)
  Bottom Layer w0.2: v1(122.75,95) v1(129.25,95)
EM0_B6: R6C.2 U8.87 | length 154.9
  Top Layer w0.2: v1(133,180) R6C.2@133.975,180 ; U8.87@141.571,49.175 141.598,49.175 142.273,48.5 142.75,48.5 147.25,53 147.25,74 147.65,74.4 147.65,127.2 v1(146.6,128.25)
  Bottom Layer w0.2: v1(133,180) 134.5,181.5 145.5,181.5 150.681,176.319 150.681,156.373 149.842,155.534 149.842,131.492 v1(146.6,128.25)
EM0_B8: R6D.2 U8.92 | length 155.2
  Top Layer w0.2: v1(115.5,177.75) 117.75,180 R6D.2@118.975,180 ; U8.92@140.864,54.032 141.831,55 144,55 145.5,56.5 145.5,76.25 145.9,76.65 145.9,121 145.9,121.057 v1(144.728,122.228)
  Bottom Layer w0.2: v1(115.5,177.75) 115.5,175.75 116.05,175.2 116.05,131.95 125.132,122.868 144.089,122.868 v1(144.728,122.228)
EM1_A6: R7A.2 U8.142 | length 36.9
  Top Layer w0.2: R7A.2@106.525,96.25 106.525,96.225 108.85,93.9 108.85,77.582 119,67.432 119,66.089 U8.142@120.096,64.993
EM1_A8: R7B.2 U8.124 | length 43
  Top Layer w0.2: R7B.2@121.525,96.25 122.378,96.25 122.628,96.5 v1(122.75,96.5) ; v1(129.25,96.5) 134,91.75 134,69.505 130.995,66.5 130.704,66.5 U8.124@129.55,65.346
  Bottom Layer w0.2: v1(122.75,96.5) v1(129.25,96.5)
EM1_B6: R7C.2 U8.86 | length 159.6
  Top Layer w0.2: v1(131.75,178.75) R7C.2@133.975,178.75 ; U8.86@141.217,48.821 141.245,48.821 142.041,48.025 142.865,48.025 147.7,52.86 147.7,73.7 148,74 v1(148,128.25)
  Bottom Layer w0.2: v1(131.75,178.75) 131.75,179.75 133.85,181.85 145.9,181.85 151.031,176.719 151.031,156.228 150.192,155.389 150.192,130.442 v1(148,128.25)
EM1_B8: R7D.2 U8.91 | length 154.1
  Top Layer w0.2: v1(116.175,176) 116.225,176 118.608,178.383 118.626,178.383 118.975,178.732 R7D.2@118.975,178.75 ; U8.91@141.217,53.679 142.039,54.5 144.25,54.5 145.85,56.1 145.85,75.85 146.25,76.25 146.25,121 146.25,122.687 v1(145.718,123.218)
  Bottom Layer w0.2: v1(116.175,176) 116.175,175.883 116.4,175.658 116.4,132.1 125.282,123.218 v1(145.718,123.218)
EN_A6: JP2A.2 U7A.16 | length 24
  Top Layer w0.2: U7A.16@82.5,101.102 82.527,101.075 82.527,100.473 83,100 v1(83.75,100) ; v1(93.35,83) 93.35,83.775 JP2A.2@93.5,83.925
  Bottom Layer w0.2: v1(83.75,100) 83.75,93 93.308,83.442 93.308,83.042 v1(93.35,83)
EN_A7: JP1A.2 U7A.17 | length 25.4
  Top Layer w0.2: U7A.17@83.427,102 84.25,102 84.664,101.586 84.664,101.086 v1(84.75,101) ; v1(94.75,83) JP1A.2@94.75,83.925
  Bottom Layer w0.2: v1(84.75,101) 84.75,92.505 94.255,83 v1(94.75,83)
EN_A8: JP2B.2 U7A.18 | length 43.2
  Top Layer w0.2: U7A.18@83.402,102.5 85.088,102.5 85.468,102.12 v1(85.59,102.12) ; JP2B.2@111.25,82.4 v1(111.25,83.5)
  Bottom Layer w0.2: v1(85.59,102.12) 85.59,92.16 94,83.75 95,83.75 95.825,82.925 110.8,82.925 110.941,83.066 110.941,83.069 111.25,83.378 v1(111.25,83.5)
EN_A9: JP1B.2 U7A.19 | length 42.2
  Top Layer w0.2: U7A.19@83.402,103 86.394,103 86.481,103.087 v1(86.603,103.087) ; JP1B.2@109.75,82.55 v1(109.75,83.5)
  Bottom Layer w0.2: v1(86.603,103.087) 86.603,91.642 93.995,84.25 95.5,84.25 96.25,83.5 v1(109.75,83.5)
EN_A10: D15.1 R35.2 U7A.23 U7A.26 | length 73.8
  Top Layer w0.2: U7A.26@82,106.402 82,107.411 v1(83.559,108.97) 83.593,108.97 85,107.563 85,105.75 84.25,105 U7A.23@83.402,105 ; R35.2@109.5,147.025 109.525,147 v1(110.5,147) 110.586,146.914 110.586,146.654 113.15,144.091 D15.1@113.15,143.858
  Bottom Layer w0.2: v1(83.559,108.97) 83.559,116.511 91.125,124.077 91.125,124.125 91.2,124.2 91.2,143.7 95.75,148.25 104.75,148.25 106,147 v1(110.5,147)
EN_A11: D15.2 R34.2 U7A.24 U7A.25 | length 68.2
  Top Layer w0.2: U7A.24@83.427,105.5 82.929,105.5 82.5,105.929 U7A.25@82.5,106.427 82.527,106.454 82.527,106.952 83.085,107.51 v1(84.24,107.51) ; R34.2@110.25,144.025 110.268,144.025 111.2,144.957 v1(111.2,144.98) 111.754,144.426 111.754,143.954 D15.2@111.85,143.858
  Bottom Layer w0.2: v1(84.24,107.51) 84.24,116.697 91.55,124.007 91.55,143.176 96.124,147.75 104.5,147.75 106.25,146 110.18,146 v1(111.2,144.98)
EN_B6: JP2C.2 U7B.16 | length 37.6
  Top Layer w0.2: v1(145,190.75) 148,193.75 JP2C.2@148,195.2 ; v1(158.75,168) 159.396,168 159.973,167.423 159.973,166.925 U7B.16@160,166.898
  Bottom Layer w0.2: v1(145,190.75) 147.5,190.75 157.75,180.5 157.75,169 v1(158.75,168)
EN_B7: JP1C.2 U7B.17 | length 37.8
  Top Layer w0.2: v1(145.84,189.63) 145.84,190.84 149.25,194.25 JP1C.2@149.25,195.2 ; v1(157.585,167.223) 157.671,167.137 157.671,166.829 158.473,166.027 159.046,166.027 U7B.17@159.073,166
  Bottom Layer w0.2: v1(145.84,189.63) 148.12,189.63 157.25,180.5 157.25,167.566 157.585,167.23 v1(157.585,167.223)
EN_B8: JP2D.2 U7B.18 | length 50.1
  Top Layer w0.2: JP2D.2@130.5,191.425 130.75,191.175 v1(130.75,187.75) ; v1(156.527,166.307) 157.334,165.5 U7B.18@159.098,165.5
  Bottom Layer w0.2: v1(130.75,187.75) 130.836,187.836 131.078,187.836 131.092,187.85 149.395,187.85 149.495,187.75 149.5,187.75 156.75,180.5 156.75,166.649 156.527,166.426 v1(156.527,166.307)
EN_B9: JP1D.2 U7B.19 | length 51.4
  Top Layer w0.2: v1(131.75,186.75) JP1D.2@131.75,191.425 ; v1(155.825,165) U7B.19@159.098,165
  Bottom Layer w0.2: v1(131.75,186.75) 132.5,187.5 149.25,187.5 156.25,180.5 156.25,167.25 155.75,166.75 155.75,165.075 v1(155.825,165)
EN_B10: D16.2 R20A.2 U7B.26 | length 53
  Top Layer w0.2: D16.2@136.1,125.108 136.1,128.862 136.5,129.262 136.5,130.75 v1(137,131.25) 137,131.275 136.5,131.775 R20A.2@136.5,132.725 ; v1(149.75,156.75) 156.5,156.75 160.5,160.75 U7B.26@160.5,161.598
  Bottom Layer w0.2: v1(137,131.25) 138.25,131.25 149.142,142.142 149.142,156.142 v1(149.75,156.75)
EN_B11: D16.1 R21A.2 U7B.25 | length 53.4
  Top Layer w0.2: D16.1@137.4,125.108 137.4,129.478 137.25,129.628 v1(137.25,129.75) 137.75,130.25 R21A.2@137.75,132.725 ; v1(150.106,158.104) 157.029,158.104 159.973,161.048 159.973,161.546 U7B.25@160,161.573
  Bottom Layer w0.2: v1(137.25,129.75) 149.492,141.992 149.492,155.679 150.325,156.512 150.325,157.763 150.106,157.982 v1(150.106,158.104)
EN_B12: D27.2 R20B.2 U7B.24 | length 62.3
  Top Layer w0.2: D27.2@120.35,132.108 120.35,135.1 121.225,135.975 R20B.2@121.225,136 121.225,136.025 122.125,136.925 122.675,136.925 v1(122.75,137) ; v1(148.25,158) 149,158.75 153.25,158.75 157,162.5 U7B.24@159.073,162.5
  Bottom Layer w0.2: v1(122.75,137) 129.692,137 129.867,137.175 143.175,137.175 148.25,142.25 v1(148.25,158)
EN_B13: D27.1 R21B.2 U7B.23 | length 62.5
  Top Layer w0.2: R21B.2@121.225,134.75 121.225,134.732 122.457,133.5 v1(122.5,133.5) 122.414,133.414 122.414,133.104 121.65,132.341 D27.1@121.65,132.108 ; v1(150,159.5) 153.25,159.5 156.75,163 U7B.23@159.098,163
  Bottom Layer w0.2: v1(122.5,133.5) 122.5,134.75 124.4,136.65 129.837,136.65 130.012,136.825 143.325,136.825 148.792,142.292 148.792,156.287 148.825,156.32 148.825,158.325 v1(150,159.5)
ETH0_CRS_DV: R180.2 U8.166 U11.18 | length 57.8
  Top Layer w0.2: R180.2@80.025,30 80.75,30 81.5,30.75 v1(81.5,31.75) 81.5,33.25 83.5,35.25 U11.18@84.683,35.25 ; v1(110.362,57.862) 110.362,57.783 111.611,56.534 U8.166@111.611,56.507
  Bottom Layer w0.2: v1(81.5,31.75) 84.213,29.037 91.225,29.037 105.75,43.561 105.75,53.25 v1(110.362,57.862)
ETH0_MDC: R184.1 U8.9 | length 19.8
  Top Layer w0.2: R184.1@93.025,42 106.204,42 U8.9@110.904,46.7
ETH0_MDIO: R181.1 U8.8 U11.36 | length 25.2
  Top Layer w0.2: U11.36@90.778,39.25 92.45,39.25 v1(93,39.8) 94.175,39.8 R181.1@94.225,39.75 ; v1(94.25,42.75) 106.247,42.75 U8.8@110.55,47.053
  Bottom Layer w0.2: v1(93,39.8) 94.25,41.05 v1(94.25,42.75)
ETH0_REF_CLK: U8.162 U11.25 | length 47.1
  Top Layer w0.2: U11.25@88.5,34.05 88.5,32.299 88.825,31.973 v1(88.825,31.851) ; v1(109.75,60.75) 109.836,60.664 110.283,60.664 U8.162@113.025,57.922
  Bottom Layer w0.2: v1(88.825,31.851) 91.351,31.851 92.25,32.75 92.321,32.821 ccw(c92.07,33.071) 92.321,33.321 92.201,33.441 cw(c92.452,33.691) 92.201,33.941 cw(c92.452,33.691) 92.702,33.941 92.821,33.822 ccw(c93.072,34.072) 93.322,33.822 94.125,34.625 104.25,44.75 104.25,55.5 109.414,60.664 109.664,60.664 v1(109.75,60.75)
ETH0_RX_ER: R176.2 U8.6 U11.17 | length 47.1
  Top Layer w0.2: R176.2@80.025,31.25 80.25,31.475 v1(80.25,32.5) 83.5,35.75 U11.17@84.683,35.75 ; v1(108.217,45.533) 108.241,45.557 108.241,46.158 U8.6@109.843,47.76
  Bottom Layer w0.2: v1(80.25,32.5) 80.25,31.75 83.5,28.5 91.184,28.5 v1(108.217,45.533)
ETH0_RXD0: R174.2 U8.165 U11.24 | length 49.5
  Top Layer w0.2: U11.24@88,34.05 87.995,34.045 87.995,30.733 v1(87.99,30.728) 87.99,28.535 R174.2@88.25,28.275 ; v1(110.177,59.25) 110.177,59.223 111,58.4 111,57.825 U8.165@111.964,56.861
  Bottom Layer w0.2: v1(87.99,30.728) 91.228,30.728 104.75,44.25 104.75,55.25 108.75,59.25 v1(110.177,59.25)
ETH0_RXD1: R175.2 U8.167 U11.23 | length 49
  Top Layer w0.2: R175.2@87,28.275 87.145,28.42 v1(87.145,29.612) 87.145,30.895 87.5,31.25 U11.23@87.5,34.05 ; v1(109.068,58.395) 109.068,58.344 U8.167@111.257,56.154
  Bottom Layer w0.2: v1(87.145,29.612) 90.612,29.612 105.25,44.25 105.25,54.578 v1(109.068,58.395)
ETH0_TX_EN: U8.163 U11.29 | length 40.2
  Top Layer w0.2: U11.29@90.561,35.75 92.728,35.75 92.878,35.6 v1(93,35.6) ; v1(108.218,60.532) 108.218,60.494 108.712,60 110.24,60 U8.163@112.672,57.568
  Bottom Layer w0.2: v1(93,35.6) 94.35,35.6 103,44.25 103,55.313 v1(108.218,60.532)
ETH0_TXD0: U8.161 U11.33 | length 47.1
  Top Layer w0.2: U11.33@90.709,37.75 92.35,37.75 v1(93,38.4) ; v1(109.475,62.123) 109.531,62.123 U8.161@113.379,58.275
  Bottom Layer w0.2: v1(93,38.4) 97.449,42.849 97.519,42.919 ccw(c97.269,43.17) 97.519,43.42 97.404,43.536 cw(c97.654,43.786) 97.404,44.036 cw(c97.654,43.786) 97.904,44.036 98.404,43.536 ccw(c98.655,43.787) 98.905,43.536 ccw(c98.655,43.787) 98.905,44.037 98.405,44.537 ; 98.405,44.537 cw(c98.655,44.787) 98.405,45.038 cw(c98.655,44.787) 98.906,45.038 99.406,44.537 ccw(c99.656,44.788) 99.906,44.537 ccw(c99.656,44.788) 99.906,45.038 99.406,45.538 cw(c99.657,45.789) 99.406,46.039 cw(c99.657,45.789) 99.907,46.039 100.407,45.539 ccw(c100.657,45.789) 100.908,45.539 ccw(c100.657,45.789) 100.908,46.039 100.407,46.54 cw(c100.658,46.79) 100.407,47.04 cw(c100.658,46.79) 100.908,47.04 101.024,46.924 ccw(c101.274,47.175) 101.524,46.924 101.75,47.15 101.75,47.5 101.75,55.5 108.373,62.123 v1(109.475,62.123)
ETH0_TXD1: U8.160 U11.32 | length 47.4
  Top Layer w0.2: U11.32@90.67,37.25 92.628,37.25 92.878,37 v1(93,37) ; v1(110.873,61.593) 110.873,61.514 113.732,58.656 U8.160@113.732,58.629
  Bottom Layer w0.2: v1(93,37) 93.426,37.426 93.998,37.998 cw(c94.248,37.747) 94.498,37.998 94.519,37.977 ccw(c94.769,38.228) 95.019,37.977 ccw(c94.769,38.228) 95.019,38.478 94.547,38.951 cw(c94.797,39.201) 94.547,39.452 cw(c94.797,39.201) 95.047,39.452 95.52,38.979 ccw(c95.77,39.229) 96.021,38.979 ccw(c95.77,39.229) 96.021,39.479 95.548,39.952 cw(c95.798,40.203) 95.548,40.453 cw(c95.798,40.203) 96.048,40.453 96.521,39.98 ccw(c96.772,40.23) 97.022,39.98 ccw(c96.772,40.23) 97.022,40.481 96.549,40.953 cw(c96.799,41.204) 96.549,41.454 cw(c96.799,41.204) 97.05,41.454 97.523,40.981 ccw(c97.773,41.231) 98.023,40.981 ccw(c97.773,41.231) 98.023,41.482 98.003,41.502 cw(c98.253,41.753) 98.003,42.003 98.426,42.426 102.65,46.65 102.65,55.9 108.298,61.548 110.828,61.548 v1(110.873,61.593)
ETH_INH: D26.2 U11.10 | length 153
  Top Layer w0.2: U11.10@84.3,39.25 83.688,39.25 83.25,39.688 83.25,40.725 83.275,40.75 v1(84.5,40.75) ; v1(220.25,40.25) 220.797,39.703 220.797,39.245 D26.2@220.9,39.142
  Layer 1 w0.5: v1(84.5,40.75) 88.956,40.75 89.156,40.95 93.476,40.95 106.926,27.5 184.684,27.5 191.684,34.5 195.184,34.5 202.584,41.9 218.6,41.9 v1(220.25,40.25)
ETH_PHY_NINT: R186.1 U8.116 | length 47.7
  Top Layer w0.2: R186.1@93.025,43.5 104.687,43.5 v1(106.468,45.282) ; v1(126.225,60.101) 127.449,61.325 131.186,61.325 U8.116@132.379,62.518
  Layer 1 w0.5: v1(106.468,45.282) 106.468,45.444 106.753,45.728 106.753,45.753 121.5,60.5 125.691,60.5 126.09,60.101 v1(126.225,60.101)
ETH_PHY_NRST: R185.1 U8.11 | length 17.6
  Top Layer w0.2: R185.1@96.025,41.25 106.868,41.25 U8.11@111.611,45.993
ETH_PHY_WAKE_IO: R188.1 U8.156 | length 32.7
  Top Layer w0.2: R188.1@93,46 v1(95.25,46) ; v1(114.25,61.75) 114.25,60.966 115.146,60.07 U8.156@115.146,60.043
  Bottom Layer w0.2: v1(95.25,46) 98.806,49.556 98.806,53.056 108.5,62.75 113.25,62.75 v1(114.25,61.75)
FAULT: R46.2 U8.174 | length 78.5
  Top Layer w0.2: v1(107.25,55.75) 107.336,55.664 107.336,55.145 108.783,53.698 U8.174@108.783,53.679 ; v1(107.41,39.13) 107.41,31.612 112.022,27 140.75,27 146.75,33 v1(148.75,33) R46.2@152.725,33
  Layer 1 w0.5: v1(107.25,55.75) 107.236,55.75 105,53.514 105,41.54 v1(107.41,39.13)
FAULT/NINT: U8.83 U9.16 | length 62.8
  Top Layer w0.2: U8.83@140.157,47.76 141.156,46.761 141.664,46.761 v1(141.75,46.675) ; v1(189.25,49.5) 198.973,49.5 199,49.473 U9.16@199,49.148 U9.16@199,48.977
  Bottom Layer w0.2: v1(141.75,46.675) 141.825,46.75 148.25,46.75 153.2,51.7 187.05,51.7 v1(189.25,49.5)
FAULT_LED: R138.1 TP40.1 U8.70 | length 22.3
  Top Layer w0.2: v1(135.5,46.6) 134.984,46.084 134.984,43.882 135.011,43.855 135.011,43.714 U8.70@135.561,43.164 ; v1(137.25,34.75) R138.1@138.225,34.75 138.225,34.775 138.925,35.475 141.055,35.475 TP40.1@142.24,34.29
  Bottom Layer w0.2: v1(135.5,46.6) 135.5,36.5 v1(137.25,34.75)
